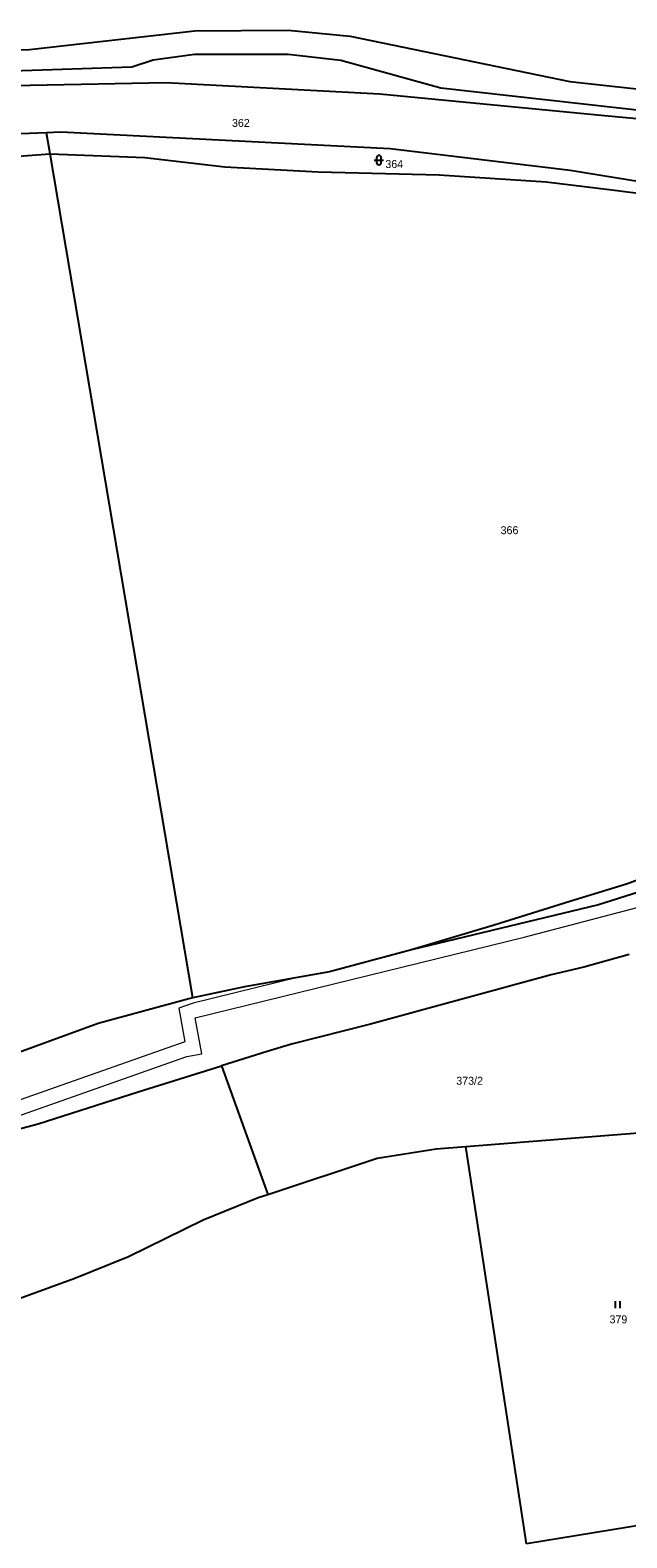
# Model space of a CAD drawing. Extents: x -769392 to -767038, y -1018329 to -1015269.
# Drawn here: x -768805 to -768677.7, y -1016436.2 to -1016114.8 of the extents above; entities that cross this region are included whole.
import ezdxf
from ezdxf.enums import TextEntityAlignment as Align

# ---------------------------------------------------------------- set-up
doc = ezdxf.new("R2010")
doc.units = 0
doc.header["$LTSCALE"] = 0.68
for name, color, linetype, lineweight in [('1', 7, 'Continuous', 25), ('13', 7, 'Continuous', 13), ('3', 7, 'Continuous', 25)]:
    doc.layers.add(name, color=color, linetype=linetype, lineweight=lineweight)
doc.layers.add('2', color=7, linetype='Continuous')

msp = doc.modelspace()

# ---------------------------------------------------------------- linework, layer by layer
at = {"layer": '1'}
for p, q in [((-768800.7, -1016141.18), (-768801.46, -1016136.73)), ((-768770.3, -1016321.1), (-768800.7, -1016141.18)), ((-768677.21, -1016311.87), (-768686.93, -1016314.55)), ((-768686.93, -1016314.55), (-768693.9, -1016316.2)), ((-768693.9, -1016316.2), (-768732.43, -1016326.7)), ((-768732.43, -1016326.7), (-768749.27, -1016331)), ((-768749.27, -1016331), (-768754.44, -1016332.51)), ((-768754.44, -1016332.51), (-768764.17, -1016335.55)), ((-768764.17, -1016335.55), (-768754.28, -1016362.98)), ((-768712.03, -1016352.77), (-768670.77, -1016349.54)), ((-768699.1, -1016437.44), (-768712.03, -1016352.77)), ((-768657.6, -1016430.72), (-768699.1, -1016437.44))]:
    msp.add_line(p, q, dxfattribs=at)
for points in [[(-769077.57, -1016120.97), (-769051.96, -1016123.35), (-768998.31, -1016124.28), (-768965.15, -1016122.6), (-768902.06, -1016120.44), (-768865.37, -1016119.73), (-768805.12, -1016118.98), (-768769.94, -1016115), (-768749.97, -1016114.84), (-768736.74, -1016116.15), (-768689.9, -1016125.81), (-768656.93, -1016129.38), (-768637.88, -1016131.28), (-768596.9, -1016133.83)], [(-768594.7, -1016141.25), (-768631.63, -1016137.21), (-768650.19, -1016134.74), (-768717.39, -1016127.21), (-768738.73, -1016121.28), (-768749.98, -1016120.03), (-768769.94, -1016120.01), (-768778.71, -1016121.23), (-768783.28, -1016122.74), (-768840.7, -1016124.64), (-768865.08, -1016124.72), (-768902.28, -1016125.77), (-768936.05, -1016127.23), (-768965.85, -1016127.81), (-768998.75, -1016129.36), (-769048.63, -1016129.62)], [(-769048.63, -1016129.62), (-769041.93, -1016130.68), (-768986.37, -1016130.93), (-768927.89, -1016128.95), (-768776.02, -1016126.01), (-768730.41, -1016128.41), (-768682.51, -1016133.05), (-768638.7, -1016137.06), (-768594.18, -1016142.99)], [(-768801.46, -1016136.73), (-768849.03, -1016138.54), (-768928.72, -1016140.13), (-768971.29, -1016140.65), (-769041.94, -1016140.83), (-769048.85, -1016140.19)], [(-768597.68, -1016159.76), (-768689.84, -1016144.77), (-768728.2, -1016140.14), (-768798.42, -1016136.61), (-768801.46, -1016136.73)], [(-769048.91, -1016143.24), (-769041.35, -1016144.34), (-769029.07, -1016146.43), (-769014.89, -1016145.59), (-769004.2, -1016144.79), (-768978.27, -1016144.96), (-768956.11, -1016144.16), (-768936.7, -1016145.55), (-768913.76, -1016146.69), (-768873.01, -1016146.55), (-768848.49, -1016146.76), (-768834.83, -1016145.72), (-768817.1, -1016142.4), (-768800.7, -1016141.18)], [(-768800.7, -1016141.18), (-768780.54, -1016141.96), (-768763.47, -1016143.95), (-768743.59, -1016145.04), (-768717.78, -1016145.65), (-768694.95, -1016147.16), (-768681.5, -1016148.79), (-768661.91, -1016151.26), (-768642.73, -1016154.07), (-768597.68, -1016159.76)], [(-768621.96, -1016276.21), (-768630.81, -1016279.41), (-768648.44, -1016285.81), (-768665.84, -1016292.42), (-768677.61, -1016296.82), (-768689.85, -1016300.54), (-768706.04, -1016305.61), (-768723.63, -1016310.87)], [(-768622.48, -1016281.86), (-768683.8, -1016301.28), (-768723.63, -1016310.87)], [(-768723.63, -1016310.87), (-768741.17, -1016315.58), (-768759.24, -1016318.77), (-768770.3, -1016321.1)], [(-768770.3, -1016321.1), (-768771.17, -1016321.28), (-768790.48, -1016326.54), (-768814.1, -1016335.18), (-768836.61, -1016342.78), (-768854.71, -1016347.34), (-768874.32, -1016349.57), (-768900.2, -1016349.59), (-768916.4, -1016348.15), (-768934.44, -1016345.54), (-768954.67, -1016341.26), (-768965.84, -1016338.63), (-769006.17, -1016326.56), (-769052.49, -1016313.52)], [(-768969.41, -1016352.62), (-768965.27, -1016353.97), (-768944.62, -1016357.5), (-768931.81, -1016359.79), (-768922.44, -1016361.14), (-768905.08, -1016362.37), (-768896.9, -1016362.82), (-768885.95, -1016362.59), (-768872.76, -1016362.19), (-768860.52, -1016361.19), (-768841.83, -1016358.19), (-768803.26, -1016347.94), (-768781.96, -1016341.13), (-768764.17, -1016335.55)], [(-768754.28, -1016362.98), (-768730.97, -1016355.3), (-768718.36, -1016353.29), (-768712.03, -1016352.77)], [(-768943.1, -1016434.71), (-768874.1, -1016408.41), (-768850.87, -1016401.4), (-768830.97, -1016394.6), (-768815.75, -1016388.24), (-768795.42, -1016380.81), (-768784, -1016376.2), (-768768.05, -1016368.44), (-768756.33, -1016363.66), (-768754.28, -1016362.98)]]:
    msp.add_lwpolyline(points, dxfattribs=at)
at = {"layer": '13'}
for points in [[(-768674.85, -1016298.44), (-768683.8, -1016301.28), (-768723.63, -1016310.87), (-768741.17, -1016315.58), (-768747.65, -1016316.72), (-768770.2, -1016322.24), (-768773.29, -1016323.31), (-768771.99, -1016330.45), (-768829.58, -1016350.73)], [(-768828.64, -1016353.7), (-768771.53, -1016333.59), (-768768.36, -1016333.01), (-768769.76, -1016325.33), (-768699.64, -1016308.19), (-768659.83, -1016297.71)]]:
    msp.add_lwpolyline(points, dxfattribs=at)
at = {"layer": '3'}
for p, q in [((-768731.091, -1016142.041), (-768731.091, -1016143.042)), ((-768730.089, -1016143.042), (-768730.089, -1016142.041)), ((-768731.591, -1016142.541), (-768729.589, -1016142.541)), ((-768680.151, -1016387.24), (-768680.151, -1016385.74)), ((-768679.15, -1016387.24), (-768679.15, -1016385.74))]:
    msp.add_line(p, q, dxfattribs=at)
for centre, start, end in [((-768730.59, -1016142.0409), 0, 180), ((-768730.59, -1016143.0409), 180, 359.98789)]:
    msp.add_arc(centre, 0.5, start, end, dxfattribs=at)

# ---------------------------------------------------------------- texts
at = {"layer": '2'}
for s, p in [('362', (-768761.94, -1016135.465)), ('364', (-768729.23, -1016144.225)), ('366', (-768704.65, -1016222.275)), ('379', (-768681.42, -1016390.465))]:
    msp.add_text(s, height=1.7, dxfattribs=at).set_placement(p)
msp.add_text('373/2', height=1.7, dxfattribs=at).set_placement((-768711.26, -1016339.615), align=Align.CENTER)

doc.saveas('drawing.dxf')
